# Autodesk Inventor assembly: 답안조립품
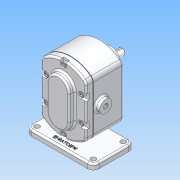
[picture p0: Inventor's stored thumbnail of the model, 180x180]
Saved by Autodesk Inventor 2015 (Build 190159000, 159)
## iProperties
Created: 2019-03
Part Number: 답안조립품
Document SubType Name: Assembly
Designer: user
Author: user
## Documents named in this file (11)
- C:\Users\user\Desktop\490307V1002\답안조립품.iam
- C:\Users\user\Desktop\490307V1002\본체.ipt
- C:\Users\user\Desktop\490307V1002\메인축.ipt
- C:\Users\user\Desktop\490307V1002\키 6 x 6 x 18.ipt
- C:\Users\user\Desktop\490307V1002\베어링부시.ipt
- C:\Users\user\Desktop\490307V1002\서브축.ipt
- C:\Users\user\Desktop\490307V1002\스퍼기어.ipt
- C:\Users\user\Desktop\490307V1002\개스킷.ipt
- C:\Users\user\Desktop\490307V1002\커버.ipt
- C:\Users\user\Desktop\490307V1002\볼트 M5.ipt
- C:\Users\user\Desktop\490307V1002\오일 실 16 28 7.ipt
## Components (1 placed, 1 different names)
1. 개스킷:1
